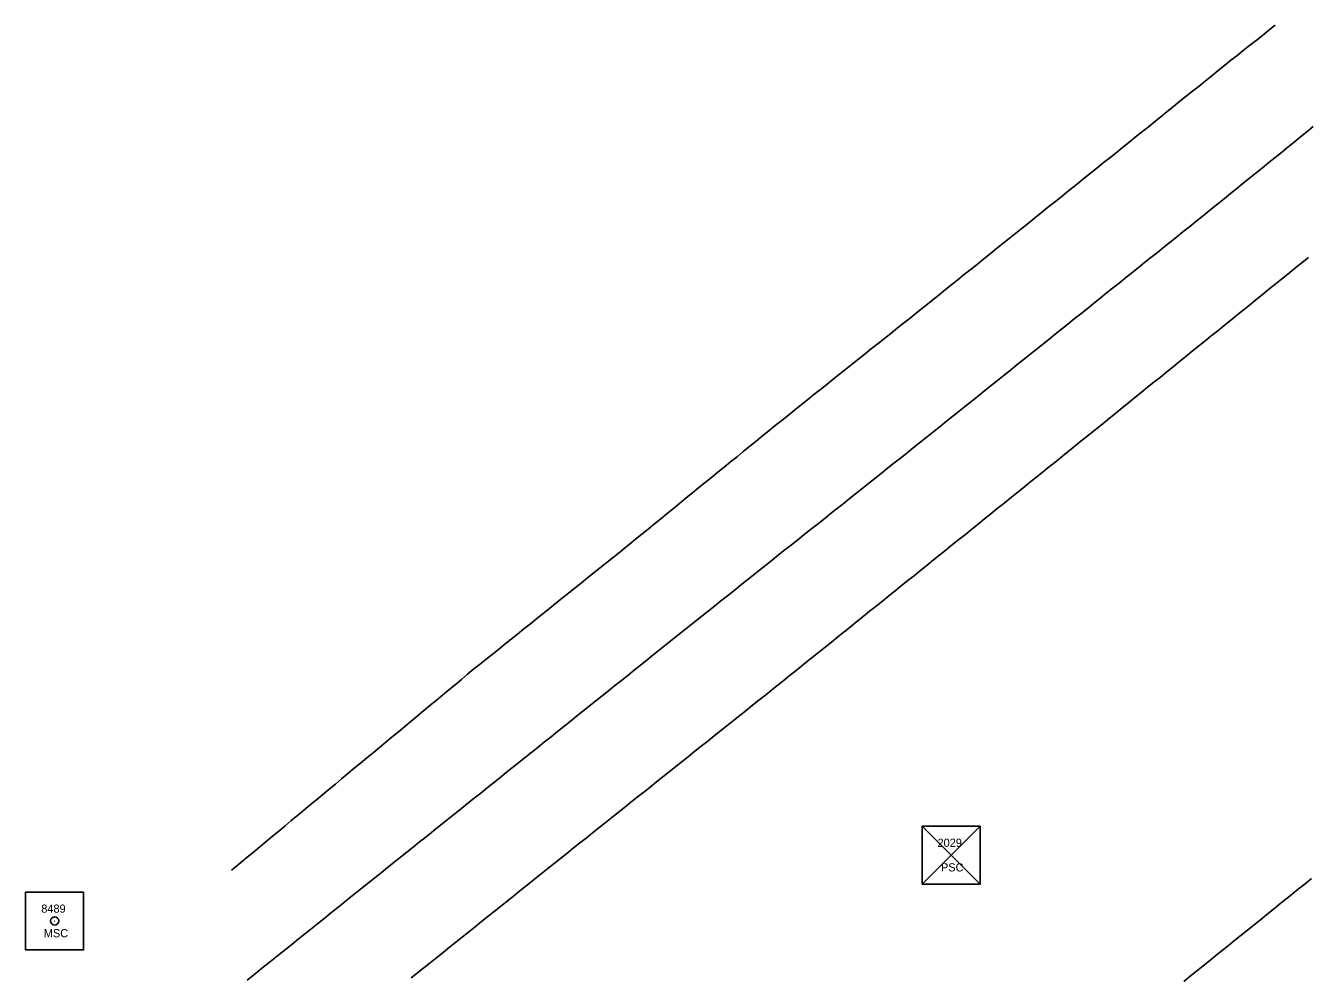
# Model space of a CAD drawing. Extents: x 205929 to 2357175, y -1785700 to 846739.
# Drawn here: x 2022464.4 to 2022621, y 806347.3 to 806463.4 of the extents above; entities that cross this region are included whole.
import ezdxf

# ---------------------------------------------------------------- set-up
doc = ezdxf.new("R2010")
doc.units = 0
for name, color, linetype in [('RD_HC_Survey', 7, 'Continuous'), ('RD_HC_txCode', 7, 'Continuous'), ('RD_Sketch1', 7, 'Continuous'), ('RD_SMD_Locator', 7, 'Continuous')]:
    doc.layers.add(name, color=color, linetype=linetype)

msp = doc.modelspace()

# ---------------------------------------------------------------- linework, layer by layer
at = {"layer": 'RD_HC_Survey'}
for p, q in [((2022573.92, 806365.68), (2022581, 806358.61)), ((2022581, 806365.68), (2022573.92, 806358.61)), ((2022581, 806365.68), (2022573.92, 806365.68)), ((2022573.92, 806365.68), (2022577.46, 806362.15)), ((2022577.46, 806362.15), (2022581, 806365.68)), ((2022577.46, 806362.15), (2022573.92, 806358.61)), ((2022581, 806358.61), (2022577.46, 806362.15)), ((2022573.92, 806358.61), (2022581, 806358.61))]:
    msp.add_line(p, q, dxfattribs=at)
for points in [[(2022581, 806365.68), (2022573.92, 806365.68), (2022573.92, 806358.61), (2022581, 806358.61)], [(2022471.48, 806357.64), (2022464.41, 806357.64), (2022464.41, 806350.57), (2022471.48, 806350.57)]]:
    msp.add_lwpolyline(points, close=True, dxfattribs=at)
msp.add_circle((2022467.95, 806354.11), 0.5, dxfattribs=at)
at = {"layer": 'RD_Sketch1'}
for points in [[(2022617.04, 806463.47), (2022616.25, 806462.85), (2022615.47, 806462.23), (2022614.69, 806461.61), (2022613.9, 806460.99), (2022613.12, 806460.37), (2022612.33, 806459.74), (2022611.63, 806459.19), (2022610.85, 806458.56), (2022610.07, 806457.93), (2022609.29, 806457.31), (2022608.51, 806456.68), (2022607.73, 806456.05), (2022606.95, 806455.43), (2022606.17, 806454.8), (2022605.4, 806454.18), (2022604.62, 806453.55), (2022603.84, 806452.92), (2022603.06, 806452.3), (2022602.28, 806451.67), (2022601.5, 806451.04), (2022600.72, 806450.42), (2022599.94, 806449.79), (2022599.16, 806449.16), (2022598.38, 806448.54), (2022597.6, 806447.91), (2022596.82, 806447.29), (2022596.04, 806446.66), (2022595.26, 806446.03), (2022594.48, 806445.41), (2022593.7, 806444.78), (2022593.7, 806444.78), (2022592.92, 806444.15), (2022592.36, 806443.7), (2022591.58, 806443.08), (2022590.8, 806442.45), (2022590.02, 806441.82), (2022589.24, 806441.2), (2022588.46, 806440.57), (2022587.68, 806439.95), (2022586.9, 806439.32), (2022586.12, 806438.69), (2022585.34, 806438.07), (2022584.56, 806437.44), (2022583.78, 806436.82), (2022583, 806436.19), (2022582.22, 806435.57), (2022581.44, 806434.94), (2022580.66, 806434.31), (2022579.88, 806433.69), (2022579.1, 806433.06), (2022578.32, 806432.44), (2022577.54, 806431.81), (2022576.76, 806431.19), (2022575.98, 806430.56), (2022575.2, 806429.93), (2022574.78, 806429.59), (2022573.99, 806428.97), (2022573.21, 806428.35), (2022572.43, 806427.72), (2022571.65, 806427.1), (2022570.87, 806426.48), (2022570.09, 806425.85), (2022569.3, 806425.23), (2022568.52, 806424.61), (2022567.74, 806423.98), (2022566.96, 806423.36), (2022566.18, 806422.73), (2022565.39, 806422.11), (2022564.61, 806421.49), (2022563.83, 806420.86), (2022563.05, 806420.24), (2022562.27, 806419.62), (2022561.49, 806418.99), (2022560.7, 806418.37), (2022559.92, 806417.75), (2022559.14, 806417.12), (2022558.36, 806416.5), (2022557.58, 806415.88), (2022556.8, 806415.25), (2022555.95, 806414.58), (2022555.18, 806413.95), (2022554.4, 806413.32), (2022553.63, 806412.69), (2022552.85, 806412.06), (2022552.07, 806411.43), (2022551.3, 806410.79), (2022550.52, 806410.16), (2022549.75, 806409.53), (2022548.97, 806408.9), (2022548.2, 806408.27), (2022547.42, 806407.64), (2022546.64, 806407.01), (2022545.87, 806406.38), (2022545.09, 806405.75), (2022544.32, 806405.12), (2022544.32, 806405.12), (2022543.54, 806404.48), (2022542.77, 806403.85), (2022541.99, 806403.22), (2022541.21, 806402.59), (2022540.44, 806401.96), (2022539.66, 806401.33), (2022538.89, 806400.7), (2022538.11, 806400.07), (2022537.76, 806399.78), (2022536.98, 806399.15), (2022536.2, 806398.53), (2022535.42, 806397.9), (2022534.64, 806397.28), (2022533.86, 806396.65), (2022533.08, 806396.02), (2022532.3, 806395.4), (2022531.52, 806394.77), (2022530.74, 806394.15), (2022529.96, 806393.52), (2022529.18, 806392.89), (2022528.4, 806392.27), (2022527.62, 806391.64), (2022526.84, 806391.02), (2022526.06, 806390.39), (2022525.28, 806389.77), (2022524.5, 806389.14), (2022523.72, 806388.51), (2022522.94, 806387.89), (2022522.16, 806387.26), (2022521.38, 806386.64), (2022520.6, 806386.01), (2022519.82, 806385.38), (2022519.17, 806384.87), (2022518.4, 806384.23), (2022517.63, 806383.59), (2022517.63, 806383.59), (2022516.86, 806382.95), (2022516.09, 806382.31), (2022515.33, 806381.68), (2022514.56, 806381.04), (2022513.79, 806380.4), (2022513.02, 806379.76), (2022512.25, 806379.12), (2022511.48, 806378.48), (2022510.71, 806377.85), (2022509.94, 806377.21), (2022509.17, 806376.57), (2022508.4, 806375.93), (2022507.63, 806375.29), (2022506.86, 806374.65), (2022506.09, 806374.01), (2022505.32, 806373.38), (2022504.55, 806372.74), (2022503.78, 806372.1), (2022503.01, 806371.46), (2022502.24, 806370.82), (2022501.47, 806370.18), (2022500.7, 806369.54), (2022499.93, 806368.91), (2022499.16, 806368.27), (2022498.39, 806367.63), (2022497.62, 806366.99), (2022496.85, 806366.35), (2022496.09, 806365.71), (2022495.32, 806365.07), (2022494.55, 806364.44), (2022493.78, 806363.8), (2022493.01, 806363.16), (2022492.24, 806362.52), (2022491.47, 806361.88), (2022490.7, 806361.24), (2022489.93, 806360.61), (2022489.55, 806360.29)], [(2022621.69, 806451.09), (2022620.91, 806450.46), (2022620.13, 806449.83), (2022619.36, 806449.21), (2022618.58, 806448.58), (2022617.8, 806447.95), (2022617.02, 806447.32), (2022616.24, 806446.69), (2022615.47, 806446.06), (2022615.47, 806446.06), (2022614.69, 806445.44), (2022613.91, 806444.81), (2022613.13, 806444.18), (2022612.36, 806443.55), (2022611.58, 806442.92), (2022610.8, 806442.29), (2022610.02, 806441.66), (2022609.24, 806441.04), (2022608.47, 806440.41), (2022607.69, 806439.78), (2022607.33, 806439.49), (2022606.55, 806438.86), (2022605.77, 806438.24), (2022604.99, 806437.61), (2022604.21, 806436.99), (2022603.43, 806436.36), (2022602.64, 806435.74), (2022601.86, 806435.11), (2022601.08, 806434.49), (2022600.3, 806433.86), (2022599.52, 806433.24), (2022598.74, 806432.61), (2022597.96, 806431.99), (2022597.18, 806431.36), (2022596.4, 806430.74), (2022595.62, 806430.11), (2022594.84, 806429.49), (2022594.06, 806428.86), (2022593.28, 806428.24), (2022592.5, 806427.61), (2022591.72, 806426.99), (2022590.94, 806426.36), (2022590.16, 806425.74), (2022589.38, 806425.11), (2022588.6, 806424.49), (2022587.82, 806423.86), (2022587.03, 806423.24), (2022586.25, 806422.61), (2022585.47, 806421.99), (2022584.69, 806421.36), (2022583.91, 806420.74), (2022583.13, 806420.11), (2022582.35, 806419.49), (2022581.57, 806418.86), (2022580.79, 806418.24), (2022580.01, 806417.61), (2022579.23, 806416.99), (2022578.45, 806416.36), (2022577.67, 806415.74), (2022576.89, 806415.11), (2022576.11, 806414.49), (2022575.94, 806414.35), (2022575.16, 806413.73), (2022574.38, 806413.11), (2022573.6, 806412.49), (2022572.81, 806411.86), (2022572.03, 806411.24), (2022571.25, 806410.62), (2022570.47, 806409.99), (2022569.68, 806409.37), (2022568.9, 806408.75), (2022568.12, 806408.13), (2022567.34, 806407.5), (2022566.55, 806406.88), (2022566.55, 806406.88), (2022565.77, 806406.26), (2022564.99, 806405.64), (2022564.21, 806405.01), (2022563.42, 806404.39), (2022562.64, 806403.77), (2022561.86, 806403.14), (2022561.08, 806402.52), (2022560.29, 806401.9), (2022559.51, 806401.28), (2022558.73, 806400.65), (2022557.95, 806400.03), (2022557.16, 806399.41), (2022556.38, 806398.79), (2022555.6, 806398.16), (2022554.82, 806397.54), (2022554.03, 806396.92), (2022553.25, 806396.29), (2022552.47, 806395.67), (2022551.69, 806395.05), (2022550.91, 806394.43), (2022550.12, 806393.8), (2022549.34, 806393.18), (2022548.56, 806392.56), (2022547.78, 806391.94), (2022546.99, 806391.31), (2022546.21, 806390.69), (2022545.43, 806390.07), (2022544.65, 806389.44), (2022543.86, 806388.82), (2022543.41, 806388.46), (2022542.63, 806387.84), (2022541.85, 806387.21), (2022541.07, 806386.59), (2022540.29, 806385.96), (2022539.51, 806385.34), (2022538.73, 806384.71), (2022537.95, 806384.09), (2022537.17, 806383.46), (2022536.38, 806382.84), (2022535.6, 806382.22), (2022534.82, 806381.59), (2022534.04, 806380.97), (2022533.26, 806380.34), (2022532.48, 806379.72), (2022531.7, 806379.09), (2022530.92, 806378.47), (2022530.14, 806377.84), (2022529.36, 806377.22), (2022528.58, 806376.59), (2022527.79, 806375.97), (2022527.01, 806375.34), (2022526.23, 806374.72), (2022525.45, 806374.09), (2022524.67, 806373.47), (2022523.89, 806372.84), (2022523.11, 806372.22), (2022522.33, 806371.6), (2022521.55, 806370.97), (2022520.77, 806370.35), (2022519.99, 806369.72), (2022519.21, 806369.1), (2022518.42, 806368.47), (2022517.64, 806367.85), (2022516.86, 806367.22), (2022516.86, 806367.22), (2022516.08, 806366.6), (2022515.3, 806365.97), (2022514.52, 806365.35), (2022513.74, 806364.72), (2022512.96, 806364.1), (2022512.53, 806363.75), (2022511.75, 806363.13), (2022510.97, 806362.5), (2022510.18, 806361.88), (2022509.4, 806361.25), (2022508.62, 806360.63), (2022507.84, 806360), (2022507.06, 806359.38), (2022506.28, 806358.75), (2022505.5, 806358.13), (2022504.72, 806357.5), (2022503.94, 806356.88), (2022503.16, 806356.25), (2022502.38, 806355.62), (2022501.6, 806355), (2022500.82, 806354.37), (2022500.04, 806353.75), (2022499.26, 806353.12), (2022498.48, 806352.5), (2022497.7, 806351.87), (2022496.92, 806351.25), (2022496.14, 806350.62), (2022495.36, 806350), (2022494.58, 806349.37), (2022493.8, 806348.75), (2022493.02, 806348.12), (2022492.24, 806347.5), (2022491.45, 806346.87)], [(2022621.1, 806435.12), (2022620.32, 806434.49), (2022620.12, 806434.34), (2022619.34, 806433.71), (2022618.57, 806433.08), (2022617.79, 806432.45), (2022617.01, 806431.82), (2022616.23, 806431.2), (2022615.46, 806430.57), (2022614.68, 806429.94), (2022613.9, 806429.31), (2022613.12, 806428.68), (2022612.34, 806428.05), (2022611.57, 806427.43), (2022610.79, 806426.8), (2022610.01, 806426.17), (2022609.23, 806425.54), (2022608.45, 806424.91), (2022607.68, 806424.28), (2022606.9, 806423.66), (2022606.12, 806423.03), (2022605.34, 806422.4), (2022604.57, 806421.77), (2022603.79, 806421.14), (2022603.01, 806420.51), (2022602.23, 806419.89), (2022601.45, 806419.26), (2022600.68, 806418.63), (2022599.9, 806418), (2022599.12, 806417.37), (2022598.34, 806416.74), (2022597.56, 806416.12), (2022596.79, 806415.49), (2022596.01, 806414.86), (2022595.23, 806414.23), (2022594.45, 806413.6), (2022593.68, 806412.97), (2022592.9, 806412.35), (2022592.12, 806411.72), (2022591.34, 806411.09), (2022590.56, 806410.46), (2022590.1, 806410.09), (2022589.32, 806409.46), (2022588.54, 806408.83), (2022587.76, 806408.21), (2022586.98, 806407.58), (2022586.2, 806406.95), (2022585.42, 806406.33), (2022584.64, 806405.7), (2022584.64, 806405.7), (2022583.87, 806405.07), (2022583.09, 806404.45), (2022582.31, 806403.82), (2022581.53, 806403.19), (2022580.75, 806402.57), (2022579.97, 806401.94), (2022579.19, 806401.31), (2022578.41, 806400.69), (2022577.63, 806400.06), (2022576.85, 806399.43), (2022576.07, 806398.81), (2022575.29, 806398.18), (2022574.51, 806397.55), (2022573.74, 806396.93), (2022572.96, 806396.3), (2022572.18, 806395.67), (2022571.4, 806395.05), (2022570.62, 806394.42), (2022569.84, 806393.79), (2022569.06, 806393.17), (2022568.28, 806392.54), (2022567.5, 806391.91), (2022566.72, 806391.29), (2022565.94, 806390.66), (2022565.16, 806390.03), (2022564.38, 806389.41), (2022563.61, 806388.78), (2022562.83, 806388.15), (2022562.05, 806387.53), (2022561.27, 806386.9), (2022560.49, 806386.27), (2022559.71, 806385.65), (2022558.93, 806385.02), (2022558.15, 806384.39), (2022557.88, 806384.18), (2022557.1, 806383.56), (2022556.32, 806382.93), (2022555.54, 806382.31), (2022554.76, 806381.68), (2022553.98, 806381.06), (2022553.19, 806380.44), (2022552.41, 806379.81), (2022551.63, 806379.19), (2022550.85, 806378.57), (2022550.07, 806377.94), (2022549.28, 806377.32), (2022548.5, 806376.7), (2022547.72, 806376.07), (2022546.94, 806375.45), (2022546.16, 806374.83), (2022545.38, 806374.2), (2022544.59, 806373.58), (2022543.81, 806372.96), (2022543.03, 806372.33), (2022542.25, 806371.71), (2022541.47, 806371.09), (2022540.68, 806370.46), (2022539.9, 806369.84), (2022539.12, 806369.22), (2022538.34, 806368.59), (2022537.56, 806367.97), (2022536.78, 806367.35), (2022535.99, 806366.72), (2022535.21, 806366.1), (2022535.21, 806366.1), (2022534.43, 806365.47), (2022533.65, 806364.85), (2022532.87, 806364.23), (2022532.08, 806363.6), (2022531.3, 806362.98), (2022530.52, 806362.36), (2022529.74, 806361.73), (2022528.96, 806361.11), (2022528.18, 806360.49), (2022527.39, 806359.86), (2022526.61, 806359.24), (2022526.33, 806359.02), (2022525.55, 806358.39), (2022524.77, 806357.77), (2022523.99, 806357.14), (2022523.21, 806356.52), (2022522.43, 806355.89), (2022521.65, 806355.27), (2022520.87, 806354.64), (2022520.09, 806354.02), (2022519.31, 806353.39), (2022518.53, 806352.76), (2022517.74, 806352.14), (2022516.96, 806351.51), (2022516.18, 806350.89), (2022515.4, 806350.26), (2022514.62, 806349.64), (2022513.84, 806349.01), (2022513.06, 806348.39), (2022512.28, 806347.76), (2022511.5, 806347.14)], [(2022621.46, 806359.27), (2022620.68, 806358.65), (2022619.9, 806358.02), (2022619.12, 806357.39), (2022618.35, 806356.77), (2022617.57, 806356.14), (2022616.79, 806355.51), (2022616.01, 806354.89), (2022615.23, 806354.26), (2022614.45, 806353.63), (2022613.67, 806353), (2022612.89, 806352.38), (2022612.11, 806351.75), (2022611.33, 806351.12), (2022610.56, 806350.5), (2022609.78, 806349.87), (2022609, 806349.24), (2022608.22, 806348.61), (2022607.44, 806347.99), (2022606.66, 806347.36), (2022605.88, 806346.73)]]:
    msp.add_lwpolyline(points, dxfattribs=at)
at = {"layer": 'RD_SMD_Locator'}
for centre in [(2022577.46, 806362.15), (2022467.95, 806354.11)]:
    msp.add_circle(centre, 0.001, dxfattribs=at)

# ---------------------------------------------------------------- texts
at = {"layer": 'RD_HC_txCode'}
for s, p in [('2029', (2022575.79, 806363.15)), ('PSC', (2022576.21, 806360.15)), ('8489', (2022466.32, 806355.11)), ('MSC', (2022466.63, 806352.11))]:
    msp.add_text(s, height=1, dxfattribs=at).set_placement(p)

doc.saveas('drawing.dxf')
